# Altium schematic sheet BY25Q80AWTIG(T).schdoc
size 127 x 101 mm
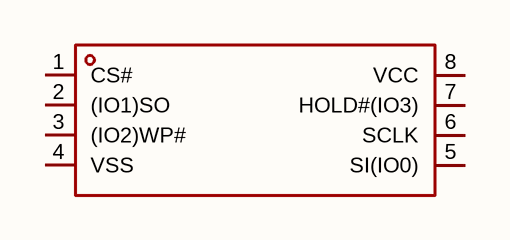
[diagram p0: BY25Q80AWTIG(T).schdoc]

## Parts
U?  by25q80awtig(t)  [SOP-8_L4.9-W3.9-P1.27-LS6.0-BL]  (value not drawn)

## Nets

Not connected (* = marked no-connect by the designer): U? 1(CS#) 2((IO1)SO) 3((IO2)WP#) 4(VSS) 5(SI(IO0)) 6(SCLK) 7(HOLD#(IO3)) 8(VCC)

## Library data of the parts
U? = by25q80awtig(t): 接口类型:SPI;存储容量:8Mbit;时钟频率(fc):100MHz;; Manufacturer: BOYAMICRO(博雅); AddInBom: yes; ModelId: 75c24a7891ee4dd6bdac16a7163ff87e; ModelName: SOP-8_L4.9-W3.9-P1.27-LS6.0-BL-1; ModelTransform: 192.913,236.22,0,0,0,0,-0.393,2.749,0; Interface: SPI; Memory Size: 8Mbit; Clock Frequency: 100MHz; Voltage - Supply: 1.65V~3.6V; Standby Supply Current: 0.6uA; Program / Erase Cycles: 100000次; Page Programming Time (Tpp): 2ms; Block Erase Time(tBE): 8ms; Data Retention - TDR (Year): 20年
